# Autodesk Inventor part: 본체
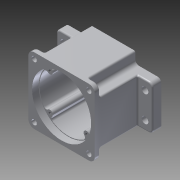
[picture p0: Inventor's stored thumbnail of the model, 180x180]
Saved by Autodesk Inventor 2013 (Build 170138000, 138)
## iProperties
Created: 2015-07
Part Number: 본체
Material: 알루미늄 6061
Document SubType Name: Modeling
Designer: user
Density: 1 g/cm^3
Author: user
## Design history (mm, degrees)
sketch "스케치1"
  geometry: L1 (-45, -45)-(45, -45); L2 (45, -45)-(45, 45); L3 (45, 45)-(-45, 45); L4 (-45, 45)-(-45, -45); 3 further points
  constraints: 8 end point, 2 midpoint, 2 parallel, 1 horizontal, 1 horizontal alignment, 1 perpendicular, 1 vertical alignment
  dimensions: "d0" = 90 distance of L3.end L2.end; "d1" = 90 distance of L2.end L1.end
extrude "돌출1" new body sketch "스케치1" distance "d2" = 70; taper "d3" = 0 deg
sketch "스케치2"
  geometry: L1 (-45, 45)-(-45, -45) reference; L2 (-45, 0)-(-45, 30); L3 (-45, 0)-(-45, -30); L4 (-45, -30)-(-65, -30); L5 (-65, -30)-(-65, 30); L6 (-65, 30)-(-45, 30); 1 further point
  constraints: 10 end point, 3 perpendicular, 2 point on line, 1 midpoint
  dimensions: "d4" = 30 distance of L2.start L2.end; "d5" = 30 distance of L2.start L3.end; "d6" = 20 distance of L3.end L4.end
extrude "돌출2" join sketch "스케치2" distance "d7" = 12; taper "d8" = 0 deg
node "작업 평면1"
sketch "스케치3"
  geometry: L1 (-45, 45)-(-45, 30) reference; L2 (65, 30)-(65, -30) reference; L3 (45, 30)-(65, 30) reference; L4 (45, 30)-(45, 45) reference; L5 (-30, 45)-(-30, 30); L6 (-30, 30)-(-45, 30); L7 (-45, 45)-(-30, 45); L8 (-45, 30)-(-45, 45); 1 further point
  constraints: 8 end point, 2 parallel, 1 collinear, 1 perpendicular
  dimensions: "d10" = 95 distance between parallel lines of L2 L5
extrude "돌출3" cut sketch "스케치3" distance "d11" = 63; taper "d12" = 0 deg
node "작업 평면2"
sketch "스케치4"
  geometry: C1 r 40 at (0, 0); 1 further point
  constraints: 1 centre point, 1 coincident
  dimensions: "d13" = 80 diameter of C1
extrude "돌출4" cut sketch "스케치4" distance "d14" = 9; taper "d15" = 0 deg
sketch "스케치5"
  geometry: C1 r 40 at (0, 0) reference; C2 r 39 at (0, 0)
  constraints: 1 centre point, 1 coincident
  dimensions: "d16" = 78 diameter of C2
extrude "돌출5" cut sketch "스케치5" distance "d17" = 52; taper "d18" = 0 deg
sketch "스케치6"
  geometry: L1 (0, 0)-(0, 11); L2 (0, 0)-(0, -20); C1 r 39 at (0, 0) reference; A1 r 20.5 centre (0, 11) between (11.115, -6.225) and (-11.115, -6.225); A2 r 14 centre (0, -20) between (-10.493, -10.732) and (10.493, -10.732); A3 r 3 centre (-12.742, -8.746) between (-10.493, -10.732) and (-11.115, -6.225); A4 r 3 centre (12.742, -8.746) between (11.115, -6.225) and (10.493, -10.732)
  constraints: 8 point on circle, 4 centre point, 4 end point, 4 tangent, 2 coincident, 1 collinear, 1 equal radius, 1 vertical
  dimensions: "d19" = 11 distance of L1.start L1.end; "d20" = 41 diameter of A1; "d21" = 20 distance of L1.start L2.end; "d22" = 28 diameter of A2; "d23" = 3 radius of A3
extrude "돌출6" join sketch "스케치6" distance "d24" = 7; taper "d25" = 0 deg
sketch "스케치7"
  geometry: C1 r 17.5 at (0, 11); A1 r 20.5 centre (0, 11) between (11.115, -6.225) and (-11.115, -6.225) reference; 1 further point
  constraints: 1 centre point, 1 coincident
  dimensions: "d26" = 35 diameter of C1
extrude "돌출7" cut sketch "스케치7" distance "d27" = 10; taper "d28" = 0 deg
sketch "스케치8"
  geometry: C1 r 17.5 at (0, 0) reference; C2 r 12.5 at (0, 0); 1 further point
  constraints: 1 centre point, 1 coincident
  dimensions: "d29" = 25 diameter of C2
extrude "돌출8" cut sketch "스케치8" distance "d30" = 5; taper "d31" = 0 deg
sketch "스케치9"
  geometry: C1 r 12.5 at (0, 0) reference; C2 r 16 at (0, 0); 1 further point
  constraints: 1 centre point, 1 coincident
  dimensions: "d32" = 32 diameter of C2
sketch "스케치11"
  geometry: L1 (65, 30)-(65, -30) reference; L2 (65, 30)-(30, 30) reference; C1 r 25 at (0, -11); 1 further point
  constraints: 1 centre point
  dimensions: "d35" = 50 diameter of C1; "d36" = 41 distance from line of C1.centre L2; "d37" = 65 distance from line of C1.centre L1
extrude "돌출9" join sketch "스케치11" distance "d38" = 7; taper "d39" = 0 deg
extrude "돌출10" cut sketch "스케치9" distance "d40" = 8; taper "d41" = 0 deg
sketch "스케치12"
  geometry: C1 r 11 at (0, -20); A1 r 14 centre (0, -20) between (-10.493, -10.732) and (10.493, -10.732) reference; 1 further point
  constraints: 1 centre point, 1 coincident
  dimensions: "d42" = 22 diameter of C1
extrude "돌출11" cut sketch "스케치12" distance "d43" = 7; taper "d44" = 0 deg
sketch "스케치13"
  geometry: C1 r 11 at (0, 0) reference; C2 r 9.5 at (0, 0); 1 further point
  constraints: 1 centre point, 1 coincident
  dimensions: "d45" = 19 diameter of C2
extrude "돌출12" cut sketch "스케치13" distance "d46" = 1; taper "d47" = 0 deg
fillet "모깎기1" dims "d48" = 2
sketch "스케치14"
  geometry: L1 (-38.997, -0.444)-(-42.637, -0.444); C1 r 40 at (0, 0) reference; A1 r 39 centre (0, 0) between (-39, 0) and (-38.997, -0.444); A2 r 3.5 centre (19.238, 29.836) between (21.809, 27.462) and (21.134, 32.777); A3 r 4 centre (24.749, 24.749) between (21.809, 27.462) and (27.462, 21.809); A4 r 3.5 centre (29.836, 19.238) between (32.777, 21.134) and (27.462, 21.809); A5 r 39 centre (0, 0) between (32.777, 21.134) and (21.134, 32.777)
  constraints: 10 point on circle, 6 tangent, 5 centre point, 2 end point, 1 coincident, 1 concentric, 1 horizontal
  dimensions: "d53" = 3.5 radius of A2; "d54" = 3.5 radius of A4; "d55" = 78 diameter of A5; "d56" = 4 radius of A3; "d57" = 0.44441 distance from line of C1.centre L1; "d58" = 21.57862 distance from line of A4.start L1; "d59" = 0.44441 distance from line of A1.start L1; "d60" = 42.6397 distance of L1.end C1.centre
extrude "돌출13" join sketch "스케치14" distance "d61" = 52; taper "d62" = 0 deg
sketch "스케치15"
  geometry: A1 r 4 centre (24.749, 24.749) between (21.809, 27.462) and (27.462, 21.809) reference; A2 r 4 centre (24.749, -24.749) between (27.462, -21.809) and (21.809, -27.462) reference; A3 r 4 centre (-24.749, -24.749) between (-21.809, -27.462) and (-27.462, -21.809) reference; A4 r 4 centre (-24.749, 24.749) between (-27.462, 21.809) and (-21.809, 27.462) reference
hole "구멍1" sketch "스케치15" at (24.749, 24.749), (-24.749, 24.749), (-24.749, -24.749), (24.749, -24.749) diameter "d66" = 3.459; stored, may be unused: countersink angle "d70" = 90 deg, drill point angle "d72" = 118 deg; dims "d67" = 12, "d68" = 4, "d69" = 2, "d71" = 15
fillet "모깎기2" dims "d73" = 5
sketch "스케치17"
  geometry: L1 (-45, 30)-(-45, -30) reference; L2 (-45, 30)-(-60, 30) reference; C1 r 4.5 at (-55, 17.5); 1 further point
  constraints: 1 centre point
  dimensions: "d76" = 9 diameter of C1; "d77" = 12.5 distance from line of C1.centre L2; "d78" = 10 distance from line of C1.centre L1
extrude "돌출14" cut sketch "스케치17" stored distance "d79" = 1; taper "d80" = 0 deg
sketch "스케치18"
  geometry: L1 (45, -45)-(-45, -45) reference; L2 (45, 45)-(45, -45) reference; C1 r 3.5 at (-37, 37)
  constraints: 1 centre point
  dimensions: "d83" = 7 diameter of C1; "d84" = 82 distance from line of C1.centre L2; "d85" = 82 distance from line of C1.centre L1
extrude "돌출15" cut sketch "스케치18" distance "d86" = 30; taper "d87" = 0 deg
chamfer "모따기1" distance "d88" = 1; stored, may be unused: second distance "d89" = 2, angle "d90" = 45 deg
chamfer "모따기2" distance "d91" = 1; stored, may be unused: second distance "d92" = 2, angle "d93" = 45 deg
fillet "모깎기3" dims "d94" = 0.3
fillet "모깎기4" dims "d95" = 0.3
fillet "모깎기5" dims "d96" = 0.3
fillet "모깎기6" dims "d97" = 2
fillet "모깎기7" dims "d98" = 8
fillet "모깎기8" dims "d99" = 5
fillet "모깎기9" dims "d100" = 2
fillet "모깎기10" dims "d101" = 2
fillet "모깎기11" dims "d102" = 5
fillet "모깎기12" dims "d103" = 2
fillet "모깎기13" dims "d104" = 2
fillet "모깎기14" dims "d105" = 2
fillet "모깎기15" dims "d106" = 2
sketch "스케치19"
  geometry: L1 (28, 45)-(-28, 45) reference; L2 (-30, -35)-(-30, -43) reference; L3 (0, 45)-(0, 30); 2 further points
  constraints: 2 end point, 1 coincident, 1 midpoint, 1 parallel, 1 other
  dimensions: "d107" = 15 distance of L3.start L3.end
feature "엠보싱1" sketch "스케치19" dims "d108" = 0.5, "d109" = 0
node "솔리드1"
mirror "대칭1"
mirror "대칭2"
mirror "대칭3"
pattern_circular "원형 패턴1" dims angle "d64" = 360 deg
mirror "대칭4"
mirror "대칭5"
mirror "대칭6"
mirror "대칭7"
